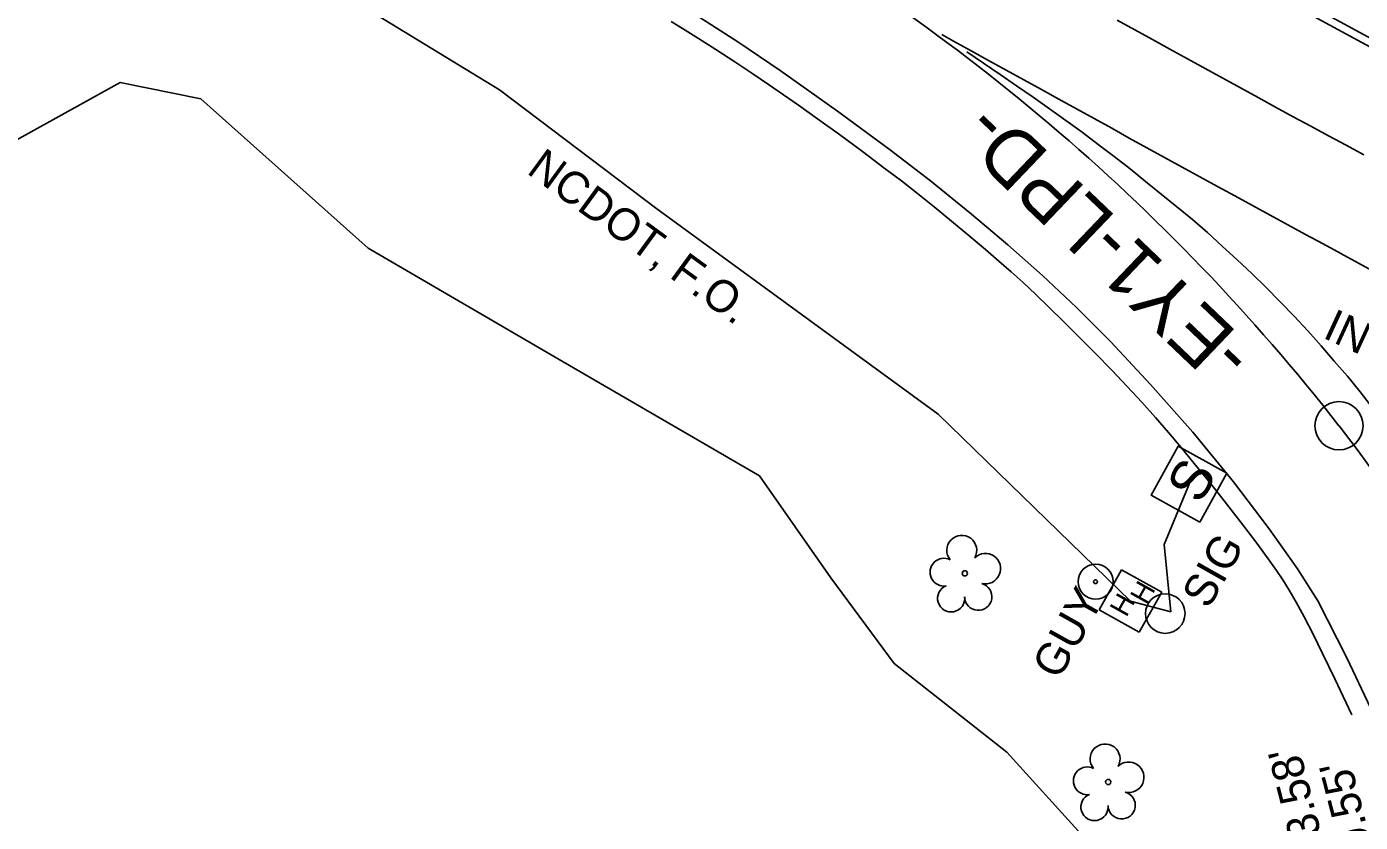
# Model space of a CAD drawing. Extents: x 2074109 to 2077820, y 741079 to 746031.
# Drawn here: x 2075614.7 to 2075780.7, y 743124.8 to 743223.8 of the extents above; entities that cross this region are included whole.
import ezdxf

# ---------------------------------------------------------------- set-up
doc = ezdxf.new("R2010")
doc.units = 0
for name, color, linetype in [('Exist Horizontal Alignment', 7, 'Continuous'), ('Exist Horizontal Alignment Direction Label', 7, 'Continuous'), ('Exist Horizontal Alignment Point', 7, 'Continuous'), ('Exist Other Culture Anchor (Guy Wire) CELL', 7, 'Continuous'), ('Exist Other Culture Anchor (Guy Wire) Text', 7, 'Continuous'), ('Exist Roads Curbs', 7, 'Continuous'), ('Exist Roads EOP', 7, 'Continuous'), ('Exist Roads EOT', 7, 'Continuous'), ('Exist Structure Minor Catch Basin Top Elevation', 7, 'Continuous'), ('Exist Structure Minor Pipes RCP 15 Inch Invert', 7, 'Continuous'), ('Exist Structure Minor Pipes RCP 18 Inch Invert', 7, 'Continuous'), ('Exist Utilities Other Pole CELL', 7, 'Continuous'), ('Exist Utilities Other Pole Text', 7, 'Continuous'), ('Exist Utilities Other Traffic Signal Box CELL', 7, 'Continuous'), ('Exist Utilities Power UG Cable SUE LOS B', 7, 'Continuous'), ('Exist Utilities Telephone Hand Hole CELL', 7, 'Continuous'), ('Exist Utilities Telephone UG FO SUE LOS B', 7, 'Continuous'), ('Exist Utilities Telephone UG FO SUE LOS B Text', 7, 'Continuous'), ('Exist Vegetation Tree CELL', 7, 'Continuous'), ('Exist Vegetation Woods Line', 7, 'Continuous')]:
    doc.layers.add(name, color=color, linetype=linetype)

msp = doc.modelspace()

# ---------------------------------------------------------------- linework, layer by layer
at = {"layer": 'Exist Horizontal Alignment'}
for centre, radius, start, end in [((2075576.49, 743016.9), 255.61, 37.9648, 61.3572), ((2075650.14, 743074.36), 162.2, 154.1155, 37.9648)]:
    msp.add_arc(centre, radius, start, end, dxfattribs=at)
at = {"layer": 'Exist Horizontal Alignment Point'}
msp.add_circle((2075778.01, 743174.14), 3, dxfattribs=at)
at = {"layer": 'Exist Other Culture Anchor (Guy Wire) CELL'}
for radius in [2.18, 0.24]:
    msp.add_circle((2075747.71, 743154.72), radius, dxfattribs=at)
at = {"layer": 'Exist Roads Curbs'}
for points in [[(2075787.48, 743219.36), (2075778.16, 743224.43), (2075768.48, 743229.7), (2075758.64, 743235.04), (2075749.64, 743239.94), (2075741.83, 743244.22), (2075733.99, 743248.48), (2075725.65, 743252.97), (2075717.6, 743257.33), (2075710.16, 743261.43), (2075703.15, 743265.28), (2075696.44, 743268.94), (2075688.69, 743273.18), (2075679.42, 743278.27), (2075670.77, 743283.02), (2075663.5, 743286.98), (2075655.6, 743291.3), (2075647.27, 743295.9)], [(2075779.6, 743138.15), (2075777.48, 743142.62), (2075775.97, 743145.78), (2075774.78, 743148.17), (2075773.66, 743150.33), (2075772.66, 743152.18), (2075771.8, 743153.67), (2075771.02, 743154.94), (2075770.24, 743156.11), (2075769.2, 743157.58), (2075767.64, 743159.69), (2075765.74, 743162.19), (2075763.73, 743164.78), (2075761.76, 743167.27), (2075759.99, 743169.45), (2075758.36, 743171.43), (2075756.77, 743173.3), (2075755.16, 743175.16), (2075753.46, 743177.07), (2075751.66, 743179.04), (2075749.72, 743181.08), (2075747.71, 743183.15), (2075745.68, 743185.19), (2075743.71, 743187.13), (2075741.91, 743188.9), (2075740.25, 743190.51), (2075738.7, 743191.96), (2075737.2, 743193.31), (2075735.69, 743194.64), (2075734, 743196.08), (2075731.98, 743197.78), (2075729.79, 743199.6), (2075727.63, 743201.39), (2075725.53, 743203.08), (2075723.54, 743204.62), (2075721.37, 743206.27), (2075718.71, 743208.28), (2075715.86, 743210.4), (2075713.12, 743212.36), (2075710.72, 743214.05), (2075708.87, 743215.35), (2075707.14, 743216.55), (2075705.07, 743217.95), (2075702.8, 743219.45), (2075700.45, 743220.99), (2075698.31, 743222.36), (2075696.65, 743223.4), (2075694.91, 743224.48)]]:
    msp.add_lwpolyline(points, dxfattribs=at)
at = {"layer": 'Exist Roads EOP'}
for points in [[(2075646.8, 743295.06), (2075650, 743293.28), (2075655.11, 743290.46), (2075661.6, 743286.92), (2075669.3, 743282.74), (2075678.05, 743277.98), (2075687.05, 743273.07), (2075695.48, 743268.46), (2075703.96, 743263.83), (2075713.12, 743258.84), (2075721.44, 743254.3), (2075727.43, 743251.02), (2075733.33, 743247.78), (2075741.41, 743243.37), (2075750.46, 743238.44), (2075759.26, 743233.65), (2075768, 743228.89), (2075776.89, 743224.04), (2075786.29, 743218.9)], [(2075781.94, 743139), (2075778.99, 743145.25), (2075775.37, 743152.33), (2075772.85, 743156.31), (2075769.31, 743161.31), (2075764.87, 743167.17), (2075759.83, 743173.33), (2075754.53, 743179.29), (2075749.58, 743184.62), (2075745.34, 743188.85), (2075741.09, 743192.87), (2075736.81, 743196.67), (2075732.29, 743200.5), (2075727.16, 743204.65), (2075722.01, 743208.58), (2075715.59, 743213.31), (2075708.44, 743218.37), (2075703.2, 743221.94), (2075698.33, 743225.08)]]:
    msp.add_lwpolyline(points, dxfattribs=at)
at = {"layer": 'Exist Roads EOT'}
for points in [[(2075750.39, 743224.64), (2075752.59, 743223.44), (2075754.78, 743222.24), (2075756.97, 743221.04), (2075759.17, 743219.84), (2075761.36, 743218.64), (2075763.55, 743217.44), (2075765.74, 743216.23), (2075767.93, 743215.02), (2075770.11, 743213.81), (2075772.31, 743212.61), (2075774.51, 743211.43), (2075776.71, 743210.25), (2075778.91, 743209.06), (2075781.12, 743207.88)], [(2075782.62, 743193.18), (2075780.43, 743194.39), (2075778.23, 743195.58), (2075776.04, 743196.78), (2075773.84, 743197.97), (2075771.65, 743199.17), (2075769.45, 743200.37), (2075767.26, 743201.56), (2075765.06, 743202.76), (2075762.87, 743203.95), (2075760.67, 743205.15), (2075758.48, 743206.35), (2075756.29, 743207.55), (2075754.1, 743208.76), (2075751.91, 743209.97), (2075749.72, 743211.18), (2075747.53, 743212.39), (2075745.34, 743213.59), (2075743.15, 743214.8), (2075740.97, 743216.01), (2075738.78, 743217.22), (2075736.59, 743218.43), (2075734.4, 743219.63), (2075732.21, 743220.84), (2075730.02, 743222.05), (2075728.56, 743222.85)], [(2075731.69, 743220.7), (2075733.75, 743219.29), (2075735.82, 743217.88), (2075737.88, 743216.47), (2075739.94, 743215.05), (2075741.97, 743213.59), (2075744, 743212.14), (2075746.04, 743210.68), (2075748.03, 743209.17), (2075750.01, 743207.65), (2075752, 743206.14), (2075753.94, 743204.56), (2075755.88, 743202.99), (2075757.83, 743201.41), (2075759.77, 743199.84), (2075761.66, 743198.21), (2075763.49, 743196.51), (2075765.32, 743194.81), (2075767.16, 743193.11), (2075768.95, 743191.36), (2075770.7, 743189.58), (2075772.45, 743187.79), (2075774.15, 743185.96), (2075775.79, 743184.08), (2075777.43, 743182.19), (2075779.08, 743180.31), (2075780.65, 743178.37), (2075782.18, 743176.39)]]:
    msp.add_lwpolyline(points, dxfattribs=at)
at = {"layer": 'Exist Utilities Other Pole CELL'}
msp.add_circle((2075756.39, 743150.75), 2.46, dxfattribs=at)
at = {"layer": 'Exist Utilities Other Traffic Signal Box CELL'}
msp.add_line((2075759.35, 743166.87), (2075759.35, 743166.87), dxfattribs=at)
msp.add_lwpolyline([(2075760.71, 743162.15), (2075764.07, 743168.23), (2075757.99, 743171.59), (2075754.63, 743165.51), (2075760.71, 743162.15)], dxfattribs=at)
at = {"layer": 'Exist Utilities Power UG Cable SUE LOS B'}
msp.add_lwpolyline([(2075757.1, 743150.97), (2075756.23, 743159.34), (2075759.35, 743166.87)], dxfattribs=at)
at = {"layer": 'Exist Utilities Telephone Hand Hole CELL'}
for p, q in [((2075750.94, 743156.21), (2075748.14, 743151.21)), ((2075755.94, 743153.41), (2075750.94, 743156.21)), ((2075753.14, 743148.42), (2075755.94, 743153.41)), ((2075752.04, 743152.31), (2075752.04, 743152.31)), ((2075748.14, 743151.21), (2075753.14, 743148.42))]:
    msp.add_line(p, q, dxfattribs=at)
at = {"layer": 'Exist Utilities Telephone UG FO SUE LOS B'}
msp.add_lwpolyline([(2075630.78, 743232.97), (2075635.29, 743233.83), (2075657.45, 743225.75), (2075673.52, 743215.95), (2075693.1, 743201.17), (2075728.14, 743175.6), (2075752.04, 743152.31), (2075757.1, 743150.97)], dxfattribs=at)
at = {"layer": 'Exist Vegetation Tree CELL'}
for p, q in [((2075731.44, 743155.76), (2075731.44, 743155.76)), ((2075749.29, 743129.78), (2075749.29, 743129.78))]:
    msp.add_line(p, q, dxfattribs=at)
for centre in [(2075731.44, 743155.76), (2075749.29, 743129.78)]:
    msp.add_circle(centre, 0.326, dxfattribs=at)
for centre, radius, start, end in [((2075731.06, 743158.63), 1.86, 330.1651, 219.7134), ((2075728.84, 743155.91), 1.73, 62.6636, 279.3457), ((2075733.99, 743156.34), 1.9, 257.1011, 134.1999), ((2075729.74, 743152.64), 1.69, 111.5671, 6.231), ((2075733.11, 743152.86), 1.7, 181.2822, 74.56), ((2075748.9, 743132.65), 1.86, 330.1651, 219.7134), ((2075751.84, 743130.37), 1.9, 257.1011, 134.1999), ((2075746.68, 743129.93), 1.73, 62.6636, 279.3457), ((2075750.96, 743126.88), 1.7, 181.2822, 74.56), ((2075747.58, 743126.66), 1.69, 111.5671, 6.231)]:
    msp.add_arc(centre, radius, start, end, dxfattribs=at)
at = {"layer": 'Exist Vegetation Woods Line'}
for points in [[(2075541.07, 743110.43), (2075553.07, 743146.49), (2075570.85, 743175.41), (2075590.67, 743195.08), (2075611.02, 743208.42), (2075626.31, 743216.89), (2075636.34, 743214.86)], [(2075636.34, 743214.86), (2075657.17, 743196.26), (2075680.97, 743182.41), (2075705.87, 743167.89), (2075714.76, 743155.2), (2075722.65, 743144.55), (2075736.65, 743133.51), (2075745.93, 743123.27)]]:
    msp.add_lwpolyline(points, dxfattribs=at)

# ---------------------------------------------------------------- texts
at = {"layer": 'Exist Horizontal Alignment Direction Label'}
msp.add_text('-EY1-LPD-', height=7, rotation=136.3094, dxfattribs=at).set_placement((2075767.76, 743183.49))
at = {"layer": 'Exist Other Culture Anchor (Guy Wire) Text'}
msp.add_text('GUY', height=4, rotation=60.742, dxfattribs=at).set_placement((2075743.14, 743142.37))
at = {"layer": 'Exist Structure Minor Catch Basin Top Elevation'}
msp.add_text("TOP=453.58'", height=4, rotation=104.3648, dxfattribs=at).set_placement((2075780.81, 743103.89))
at = {"layer": 'Exist Structure Minor Pipes RCP 15 Inch Invert'}
msp.add_text("INV OUT=450.55'", height=4, rotation=104.3648, dxfattribs=at).set_placement((2075789.83, 743091.83))
at = {"layer": 'Exist Structure Minor Pipes RCP 18 Inch Invert'}
msp.add_text("INV OUT=449.93'", height=4, rotation=335.2876, dxfattribs=at).set_placement((2075775.85, 743185.16))
at = {"layer": 'Exist Utilities Other Pole Text'}
msp.add_text('SIG', height=4, rotation=60.5812, dxfattribs=at).set_placement((2075761.77, 743151.19))
at = {"layer": 'Exist Utilities Other Traffic Signal Box CELL'}
msp.add_text('S', height=5, rotation=61.1015, dxfattribs=at).set_placement((2075760.75, 743164.23))
at = {"layer": 'Exist Utilities Telephone Hand Hole CELL'}
for p in [(2075754.07, 743151.73), (2075751.54, 743150.2)]:
    msp.add_text('H', height=2.5, rotation=60.7411, dxfattribs=at).set_placement(p)
at = {"layer": 'Exist Utilities Telephone UG FO SUE LOS B Text'}
msp.add_text('NCDOT, F.O.', height=4, rotation=323.8778, dxfattribs=at).set_placement((2075676.77, 743205.66))

doc.saveas('drawing.dxf')
